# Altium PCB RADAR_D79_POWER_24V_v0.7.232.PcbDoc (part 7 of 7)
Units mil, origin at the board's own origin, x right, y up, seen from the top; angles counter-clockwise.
Board outline 3110.24 x 3110.24 mil, 8 copper layers (Top Layer, GND1, SIG1, PWR1, PWR2, SIG2, GND2, Bottom Layer), stack 55.2 mil thick; 304 components, 269 nets, 1408 pads, 1367 vias.
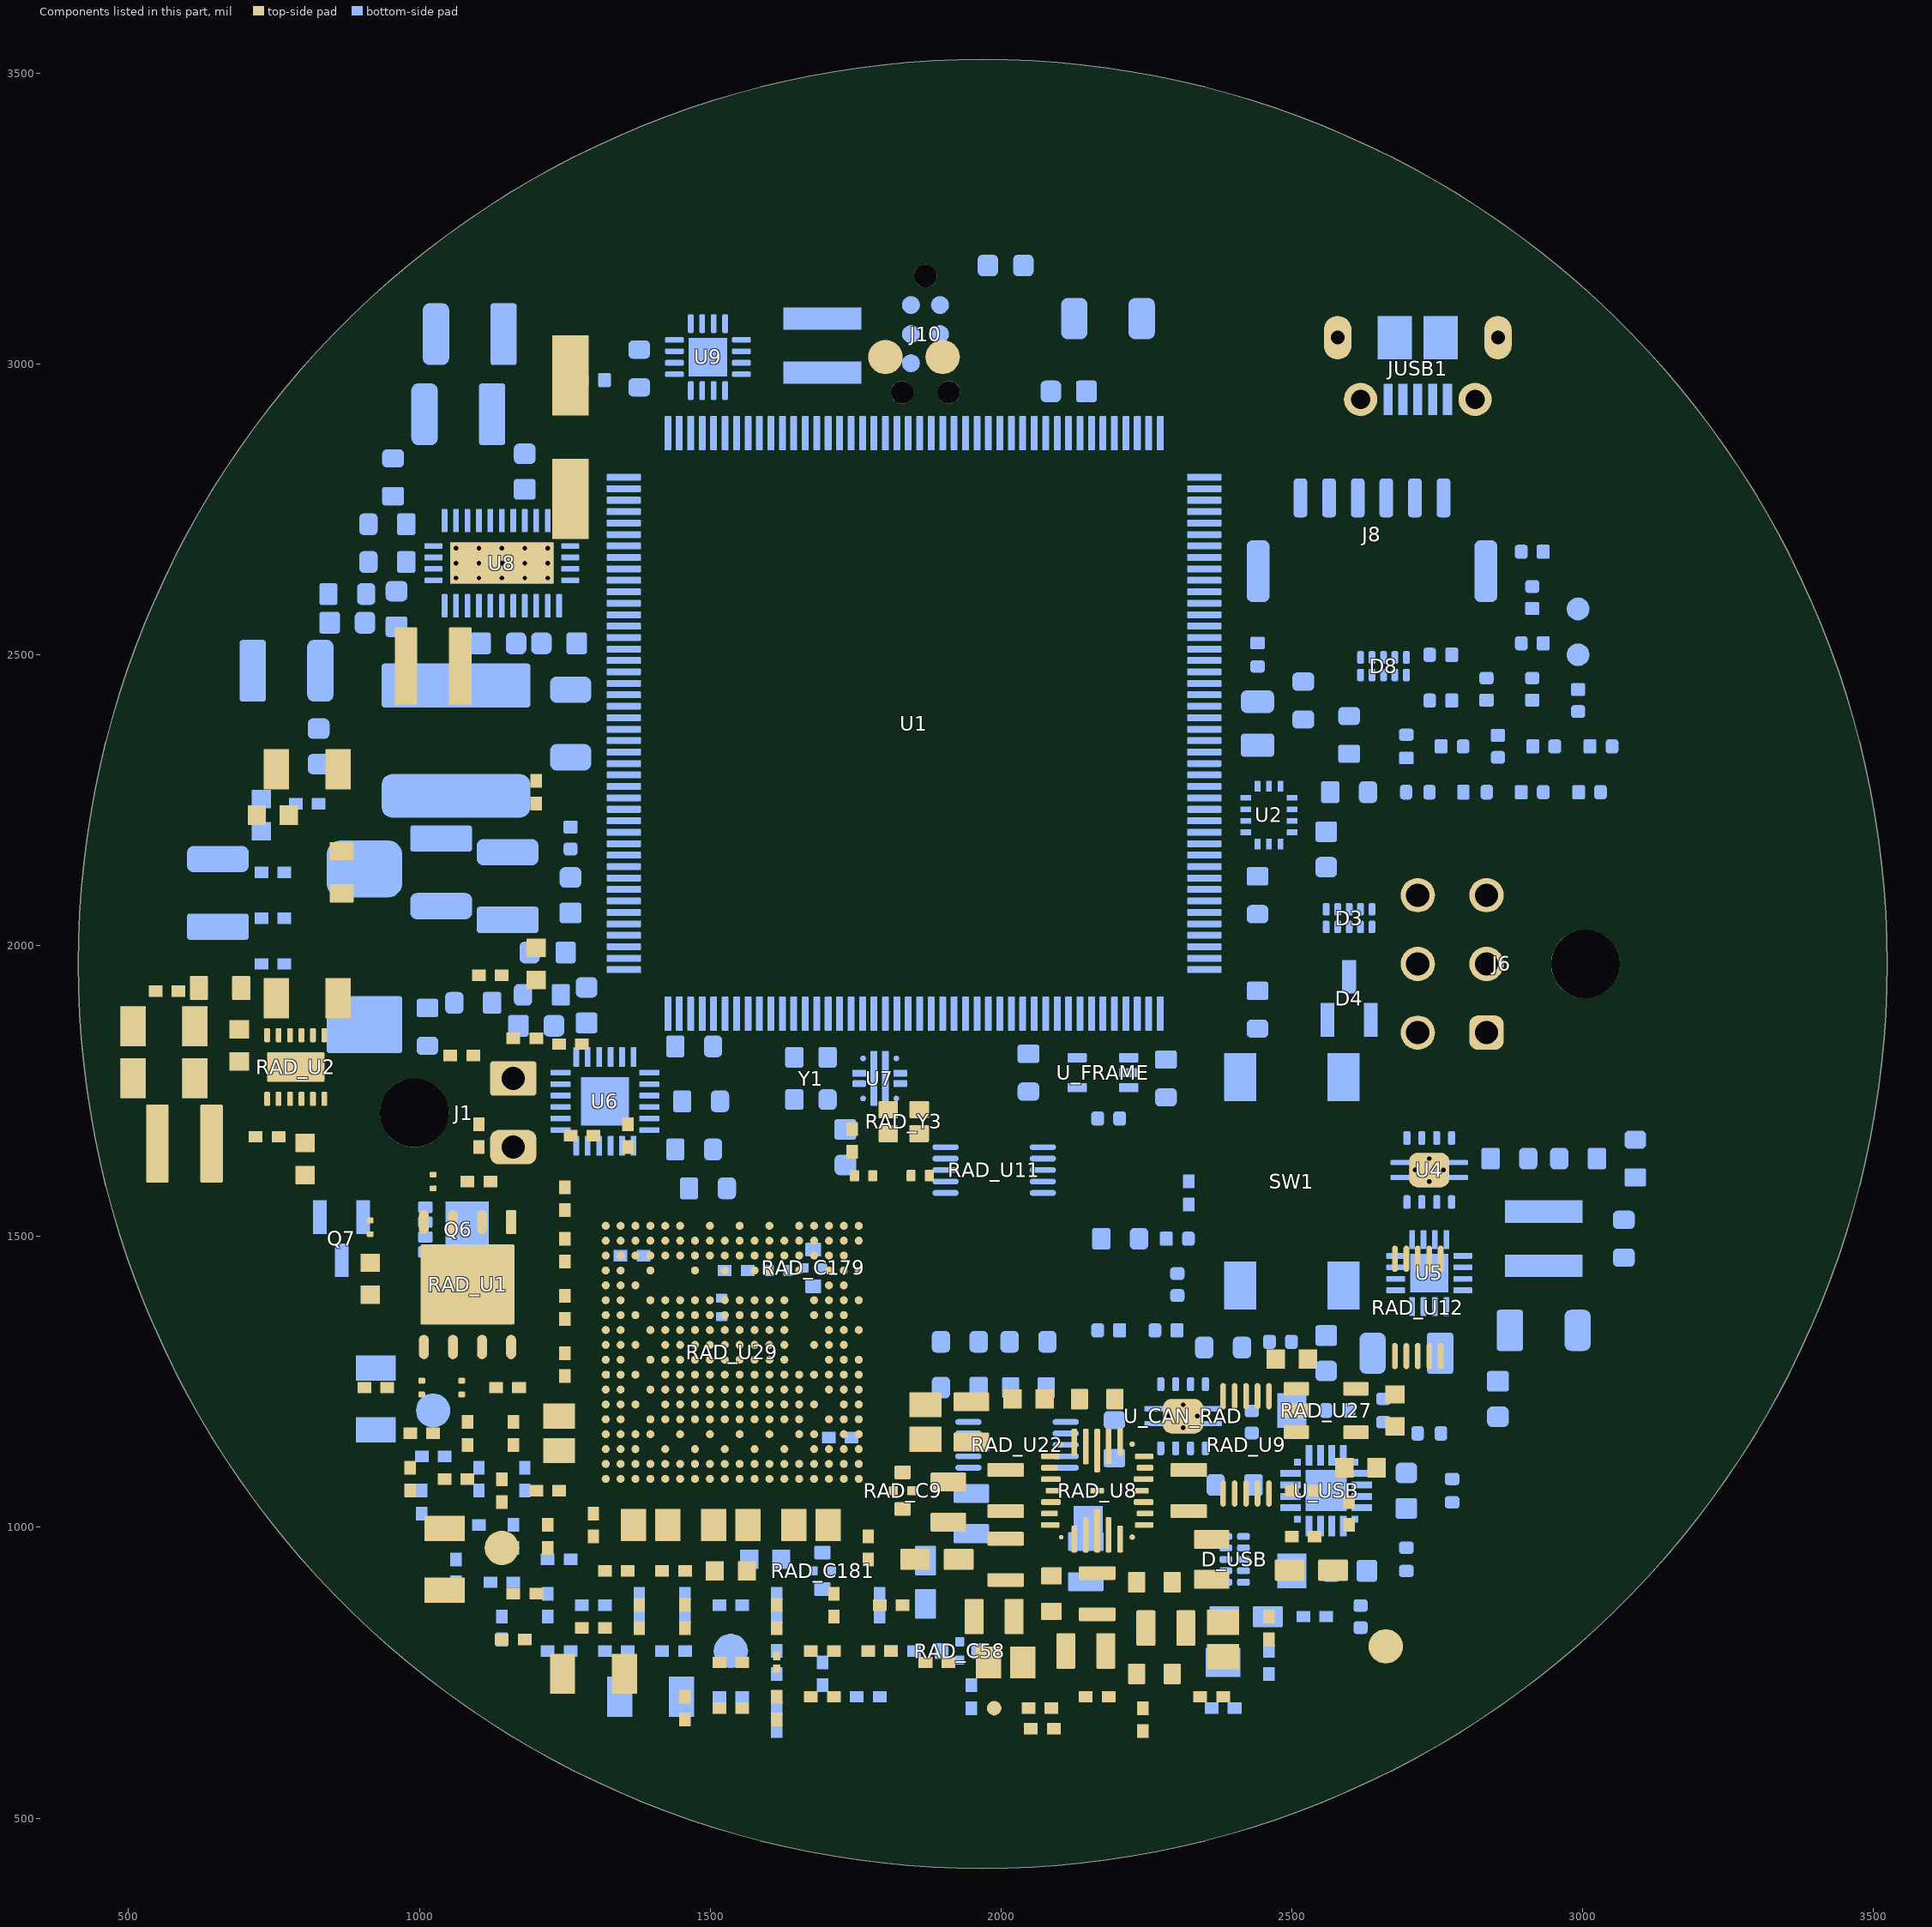
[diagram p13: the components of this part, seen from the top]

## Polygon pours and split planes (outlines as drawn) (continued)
TI_REGOUT_3V3 on PWR2 "REGOUT_3V3_WINDOW_9" (solid, pour order 9): 1746.1,974.42 1751.26,971.78 1756.65,969.65 1762.23,968.07 1767.93,967.03 1773.7,966.57 1779.5,966.66 1785.26,967.33 1790.92,968.56 1796.44,970.34 1801.75,972.65 1806.82,975.47 1811.58,978.77 1815.99,982.52 1820.02,986.69 1823.62,991.23 1826.76,996.1 1829.4,1001.26 1831.53,1006.65 1833.11,1012.23 1834.15,1017.93 1834.62,1023.7 1834.52,1029.5 1833.85,1035.26 1832.62,1040.92 1830.84,1046.44 1828.53,1051.75 1825.72,1056.82 1822.41,1061.58 1818.66,1065.99 1814.49,1070.02 1809.95,1073.62 1805.08,1076.76 1678.97,1149.43 1673.81,1152.08 1668.42,1154.2 1662.85,1155.79 1657.14,1156.82 1651.37,1157.29 1645.57,1157.19 1639.81,1156.53 1634.15,1155.3 1628.63,1153.52 1623.32,1151.21 1618.26,1148.39 1613.49,1145.09 1609.08,1141.34 1605.05,1137.17 1601.45,1132.63 1598.31,1127.76 1595.67,1122.6 1593.54,1117.21 1591.96,1111.63 1590.92,1105.93 1590.46,1100.15 1590.55,1094.36 1591.22,1088.6 1592.45,1082.94 1594.23,1077.42 1596.54,1072.11 1599.36,1067.04 1602.66,1062.28 1606.41,1057.86 1610.58,1053.84 1615.12,1050.24 1619.99,1047.1
TI_REGOUT_3V3 on PWR2 "REGOUT_3V3_WINDOW_10" (solid, pour order 10): 1580.31,1178.91 1582.2,1178.48 1584.12,1178.24 1586.05,1178.19 1587.97,1178.34 1589.88,1178.66 1591.74,1179.18 1593.54,1179.87 1595.27,1180.74 1596.9,1181.77 1598.42,1182.96 1599.83,1184.29 1601.09,1185.75 1602.2,1187.33 1603.15,1189.01 1603.94,1190.78 1604.55,1192.61 1604.97,1194.49 1605.21,1196.41 1605.26,1198.34 1605.12,1200.27 1604.79,1202.17 1604.27,1204.03 1603.58,1205.84 1602.71,1207.56 1601.68,1209.2 1600.49,1210.72 1599.16,1212.12 1597.7,1213.38 1596.12,1214.5 1594.44,1215.45 1592.68,1216.23 1590.84,1216.84 1380.7,1275.17 1378.81,1275.59 1376.9,1275.83 1374.96,1275.88 1373.04,1275.74 1371.13,1275.41 1369.27,1274.9 1367.47,1274.2 1365.74,1273.34 1364.11,1272.3 1362.59,1271.12 1361.19,1269.79 1359.92,1268.32 1358.81,1266.74 1357.86,1265.06 1357.07,1263.3 1356.47,1261.47 1356.04,1259.58 1355.8,1257.66 1355.75,1255.73 1355.89,1253.81 1356.22,1251.9 1356.74,1250.04 1357.43,1248.24 1358.3,1246.51 1359.33,1244.88 1360.52,1243.35 1361.85,1241.95 1363.31,1240.69 1364.89,1239.58 1366.57,1238.62 1368.33,1237.84 1370.17,1237.23
TI_REGOUT_3V3 on PWR2 "REGOUT_3V3_WINDOW_11" (solid, pour order 11): 1619.9,1154.71 1621.61,1153.81 1623.4,1153.08 1625.25,1152.53 1627.15,1152.16 1629.07,1151.99 1631,1152 1632.93,1152.2 1634.82,1152.59 1636.66,1153.16 1638.44,1153.91 1640.14,1154.83 1641.74,1155.91 1643.23,1157.15 1644.59,1158.52 1645.8,1160.02 1646.87,1161.63 1647.77,1163.34 1648.49,1165.13 1649.04,1166.98 1649.41,1168.88 1649.59,1170.8 1649.58,1172.74 1649.38,1174.66 1648.99,1176.55 1648.42,1178.4 1647.67,1180.18 1646.75,1181.87 1645.66,1183.47 1644.43,1184.96 1643.05,1186.32 1641.55,1187.53 1639.94,1188.6 1595.6,1214.82 1593.89,1215.72 1592.1,1216.45 1590.25,1217 1588.35,1217.36 1586.43,1217.54 1584.5,1217.53 1582.57,1217.33 1580.68,1216.94 1578.84,1216.37 1577.06,1215.62 1575.36,1214.7 1573.76,1213.61 1572.27,1212.38 1570.91,1211.01 1569.7,1209.51 1568.63,1207.89 1567.73,1206.18 1567.01,1204.39 1566.46,1202.54 1566.09,1200.65 1565.91,1198.72 1565.92,1196.79 1566.12,1194.87 1566.51,1192.98 1567.08,1191.13 1567.83,1189.35 1568.75,1187.65 1569.84,1186.05 1571.07,1184.57 1572.45,1183.21 1573.95,1181.99 1575.56,1180.93
TI_REGOUT_3V3 on PWR2 "REGOUT_3V3_WINDOW_12" (solid, pour order 12): 1761.65,1011.69 1763.08,1010.39 1764.63,1009.24 1766.29,1008.24 1768.03,1007.41 1769.85,1006.76 1771.72,1006.29 1773.63,1006 1775.56,1005.91 1777.49,1006 1779.4,1006.28 1781.28,1006.75 1783.1,1007.39 1784.85,1008.22 1786.5,1009.21 1788.06,1010.36 1789.49,1011.65 1790.79,1013.08 1791.94,1014.63 1792.94,1016.29 1793.77,1018.03 1794.42,1019.85 1794.89,1021.72 1795.18,1023.63 1795.28,1025.56 1795.18,1027.49 1794.9,1029.4 1794.44,1031.28 1793.79,1033.1 1792.96,1034.85 1791.97,1036.5 1790.82,1038.06 1789.53,1039.49 1643.86,1185.55 1642.43,1186.85 1640.88,1188.01 1639.22,1189 1637.48,1189.83 1635.66,1190.48 1633.79,1190.96 1631.88,1191.24 1629.95,1191.34 1628.02,1191.25 1626.11,1190.97 1624.23,1190.5 1622.41,1189.85 1620.67,1189.03 1619.01,1188.04 1617.45,1186.89 1616.02,1185.59 1614.72,1184.16 1613.57,1182.61 1612.57,1180.96 1611.74,1179.21 1611.09,1177.39 1610.62,1175.52 1610.33,1173.61 1610.24,1171.68 1610.33,1169.75 1610.61,1167.84 1611.08,1165.96 1611.72,1164.14 1612.55,1162.4 1613.54,1160.74 1614.69,1159.19 1615.98,1157.75
TI_REGOUT_3V3 on PWR2 "REGOUT_3V3_WINDOW_13" (solid, pour order 13): 1513.98,1087.64 1517.05,1085.29 1520.33,1083.26 1523.8,1081.56 1527.42,1080.2 1531.15,1079.21 1534.97,1078.59 1538.82,1078.35 1542.68,1078.48 1546.51,1078.99 1550.27,1079.88 1553.93,1081.13 1557.45,1082.73 1560.79,1084.67 1563.92,1086.93 1566.82,1089.48 1569.46,1092.31 1571.8,1095.38 1573.84,1098.66 1575.54,1102.13 1576.89,1105.75 1577.88,1109.49 1578.5,1113.3 1578.75,1117.15 1578.61,1121.02 1578.1,1124.85 1577.22,1128.61 1575.97,1132.26 1574.36,1135.78 1572.42,1139.12 1570.17,1142.25 1567.61,1145.15 1564.79,1147.79 1400.84,1286.28 1397.77,1288.62 1394.48,1290.66 1391.01,1292.36 1387.39,1293.71 1383.66,1294.7 1379.85,1295.32 1375.99,1295.57 1372.13,1295.43 1368.3,1294.92 1364.54,1294.03 1360.88,1292.78 1357.37,1291.18 1354.03,1289.24 1350.89,1286.99 1347.99,1284.43 1345.36,1281.61 1343.01,1278.54 1340.98,1275.25 1339.28,1271.78 1337.92,1268.16 1336.93,1264.43 1336.31,1260.62 1336.07,1256.76 1336.2,1252.9 1336.71,1249.07 1337.6,1245.31 1338.85,1241.65 1340.45,1238.14 1342.39,1234.79 1344.65,1231.66 1347.2,1228.76 1350.03,1226.12
TI_REGOUT_3V3 on PWR2 "REGOUT_3V3_WINDOW_14" (solid, pour order 14): 1565.21,1058.46 1568.68,1056.76 1572.3,1055.4 1576.03,1054.41 1579.84,1053.79 1583.7,1053.55 1587.56,1053.68 1591.39,1054.2 1595.15,1055.08 1598.81,1056.33 1602.32,1057.93 1605.66,1059.87 1608.8,1062.13 1611.7,1064.69 1614.33,1067.51 1616.68,1070.58 1618.71,1073.87 1620.41,1077.34 1621.76,1080.96 1622.75,1084.69 1623.37,1088.5 1623.62,1092.36 1623.48,1096.22 1622.97,1100.05 1622.08,1103.81 1620.83,1107.47 1619.23,1110.98 1617.29,1114.32 1615.03,1117.46 1612.48,1120.36 1609.65,1122.99 1606.58,1125.34 1603.3,1127.37 1558.43,1152.17 1554.96,1153.87 1551.34,1155.22 1547.6,1156.21 1543.79,1156.84 1539.93,1157.08 1536.07,1156.94 1532.24,1156.43 1528.48,1155.54 1524.83,1154.29 1521.31,1152.69 1517.97,1150.75 1514.84,1148.49 1511.94,1145.94 1509.3,1143.11 1506.96,1140.04 1504.92,1136.76 1503.22,1133.29 1501.87,1129.67 1500.88,1125.93 1500.26,1122.12 1500.02,1118.27 1500.15,1114.4 1500.66,1110.57 1501.55,1106.81 1502.8,1103.16 1504.4,1099.64 1506.34,1096.3 1508.6,1093.17 1511.15,1090.27 1513.98,1087.63 1517.05,1085.29 1520.34,1083.26
TI_REGOUT_3V3 on PWR2 "REGOUT_3V3_WINDOW_15" (solid, pour order 15): 1681.59,1048.86 1685.46,1048.87 1689.3,1049.25 1693.09,1050.01 1696.78,1051.14 1700.35,1052.62 1703.76,1054.45 1706.96,1056.6 1709.95,1059.06 1712.68,1061.79 1715.12,1064.78 1717.26,1068 1719.08,1071.41 1720.55,1074.98 1721.67,1078.68 1722.42,1082.47 1722.79,1086.32 1722.78,1090.18 1722.4,1094.02 1721.64,1097.81 1720.51,1101.51 1719.03,1105.08 1717.2,1108.48 1715.05,1111.69 1712.6,1114.67 1709.86,1117.4 1706.87,1119.85 1703.65,1121.99 1700.24,1123.8 1696.67,1125.28 1692.97,1126.39 1689.18,1127.14 1685.34,1127.51 1586.12,1132.24 1582.26,1132.23 1578.42,1131.85 1574.63,1131.09 1570.93,1129.96 1567.37,1128.48 1563.96,1126.65 1560.75,1124.5 1557.77,1122.04 1555.04,1119.31 1552.59,1116.32 1550.45,1113.1 1548.64,1109.69 1547.16,1106.12 1546.05,1102.42 1545.3,1098.63 1544.93,1094.79 1544.93,1090.92 1545.32,1087.08 1546.08,1083.29 1547.2,1079.59 1548.69,1076.03 1550.51,1072.62 1552.66,1069.41 1555.12,1066.43 1557.86,1063.7 1560.85,1061.26 1564.06,1059.11 1567.47,1057.3 1571.04,1055.82 1574.74,1054.71 1578.53,1053.96 1582.38,1053.59
TI_REGOUT_3V3 on PWR2 "REGOUT_3V3_WINDOW_16" (solid, pour order 16): 1753.46,993.03 1756.76,991.01 1760.24,989.34 1763.87,988.01 1767.61,987.04 1771.43,986.44 1775.28,986.22 1779.14,986.38 1782.97,986.92 1786.73,987.83 1790.37,989.1 1793.88,990.73 1797.21,992.69 1800.33,994.96 1803.21,997.54 1805.83,1000.38 1808.15,1003.46 1810.17,1006.76 1811.85,1010.24 1813.18,1013.87 1814.14,1017.61 1814.74,1021.43 1814.96,1025.28 1814.8,1029.14 1814.26,1032.97 1813.35,1036.73 1812.08,1040.37 1810.46,1043.88 1808.49,1047.21 1806.22,1050.33 1803.65,1053.21 1800.8,1055.83 1797.72,1058.15 1705.59,1120.75 1702.29,1122.76 1698.81,1124.44 1695.19,1125.77 1691.45,1126.74 1687.63,1127.34 1683.77,1127.56 1679.91,1127.4 1676.08,1126.86 1672.33,1125.95 1668.68,1124.68 1665.18,1123.05 1661.85,1121.09 1658.73,1118.82 1655.84,1116.24 1653.23,1113.4 1650.9,1110.32 1648.89,1107.02 1647.21,1103.54 1645.88,1099.91 1644.91,1096.17 1644.32,1092.35 1644.1,1088.5 1644.26,1084.63 1644.79,1080.81 1645.7,1077.05 1646.98,1073.41 1648.6,1069.9 1650.56,1066.57 1652.84,1063.45 1655.41,1060.57 1658.25,1057.95 1661.34,1055.63
GND on Bottom Layer "GND_BOTTOM_RETURN" (solid, remove dead copper, pour order 5): 3474.41,1968.5 3472.98,2034.19 3468.68,2099.75 3461.53,2165.06 3451.53,2230 3438.71,2294.44 3423.1,2358.26 3404.71,2421.34 3383.59,2483.55 3359.78,2544.79 3333.32,2604.93 3304.26,2663.85 3272.66,2721.46 3238.57,2777.63 3202.07,2832.26 3163.22,2885.24 3122.09,2936.48 3078.77,2985.88 3033.34,3033.34 2985.88,3078.77 2936.48,3122.09 2885.24,3163.22 2832.26,3202.07 2777.63,3238.57 2721.46,3272.66 2663.85,3304.26 2604.93,3333.32 2544.79,3359.78 2483.55,3383.59 2421.34,3404.71 2358.26,3423.1 2294.44,3438.71 2230,3451.53 2165.06,3461.53 2099.75,3468.68 2034.19,3472.98 1968.5,3474.41 1902.82,3472.98 1837.26,3468.68 1771.94,3461.53 1707.01,3451.53 1642.57,3438.71 1578.75,3423.1 1515.67,3404.71 1453.45,3383.59 1392.22,3359.78 1332.08,3333.32 1273.15,3304.26 1215.55,3272.66 1159.38,3238.57 1104.75,3202.07 1051.77,3163.22 1000.53,3122.09 951.13,3078.77 903.67,3033.34 858.23,2985.88 814.91,2936.48 773.79,2885.24 734.94,2832.26 698.44,2777.63 664.35,2721.46 632.75,2663.85 603.69,2604.93 577.23,2544.79 553.42,2483.55 532.3,2421.34 513.91,2358.26 498.29,2294.44 485.48,2230 475.48,2165.06 468.33,2099.75 464.03,2034.19 462.6,1968.5 464.03,1902.82 468.33,1837.26 475.48,1771.94 485.48,1707.01 498.29,1642.57 513.91,1578.75 532.3,1515.67 553.42,1453.45 577.23,1392.22 603.69,1332.08 632.75,1273.15 664.35,1215.55 698.44,1159.38 734.94,1104.75 773.79,1051.77 814.91,1000.53 858.23,951.13 903.67,903.67 951.13,858.23 1000.53,814.91 1051.77,773.79 1104.75,734.94 1159.38,698.44 1215.55,664.35 1273.15,632.75 1332.08,603.69 1392.22,577.23 1453.45,553.42 1515.67,532.3 1578.75,513.91 1642.57,498.29 1707.01,485.48 1771.94,475.48 1837.26,468.33 1902.82,464.03 1968.5,462.6 2034.19,464.03 2099.75,468.33 2165.06,475.48 2230,485.48 2294.44,498.29 2358.26,513.91 2421.34,532.3 2483.55,553.42 2544.79,577.23 2604.93,603.69 2663.85,632.75 2721.46,664.35 2777.63,698.44 2832.26,734.94 2885.24,773.79 2936.48,814.91 2985.88,858.23 3033.34,903.67 3078.77,951.13 3122.09,1000.53 3163.22,1051.77 3202.07,1104.75 3238.57,1159.38 3272.66,1215.55 3304.26,1273.15 3333.32,1332.08 3359.78,1392.22 3383.59,1453.45 3404.71,1515.67 3423.1,1578.75 3438.71,1642.57 3451.53,1707.01 3461.53,1771.94 3468.68,1837.26 3472.98,1902.82
GND on GND1 "GND1_REFERENCE" (solid, remove dead copper, pour order 3): 2635.41,3327.06 2608.25,3340.45 2547.8,3367.05 2486.25,3390.99 2423.71,3412.22 2360.3,3430.7 2296.15,3446.4 2231.37,3459.29 2166.09,3469.33 2100.44,3476.52 2034.53,3480.84 1968.5,3482.28 1902.47,3480.84 1836.57,3476.52 1770.92,3469.33 1705.64,3459.29 1640.86,3446.4 1576.71,3430.7 1513.3,3412.22 1450.76,3390.99 1389.21,3367.05 1328.75,3340.45 1269.52,3311.24 1211.61,3279.48 1155.15,3245.21 1100.24,3208.52 1046.97,3169.47 995.47,3128.13 945.81,3084.58 898.1,3038.91 852.43,2991.2 808.88,2941.54 767.54,2890.03 728.49,2836.77 691.8,2781.86 657.53,2725.39 625.77,2667.49 596.55,2608.25 569.95,2547.8 546.02,2486.25 524.79,2423.71 506.31,2360.3 490.61,2296.15 477.72,2231.37 467.68,2166.09 460.48,2100.44 456.17,2034.53 454.72,1968.5 456.17,1902.47 460.48,1836.57 467.68,1770.92 477.72,1705.64 490.61,1640.86 506.31,1576.71 524.79,1513.3 546.02,1450.76 569.95,1389.21 596.55,1328.75 625.77,1269.52 657.53,1211.61 691.8,1155.15 728.49,1100.24 767.54,1046.97 808.88,995.47 852.43,945.81 898.1,898.1 945.81,852.43 995.47,808.88 1046.97,767.54 1100.24,728.49 1155.15,691.8 1211.61,657.53 1269.52,625.77 1328.75,596.55 1389.21,569.95 1450.76,546.02 1513.3,524.79 1576.71,506.31 1640.86,490.61 1705.64,477.72 1770.92,467.68 1836.57,460.48 1902.47,456.17 1968.5,454.72 2034.53,456.17 2100.44,460.48 2166.09,467.68 2231.37,477.72 2296.15,490.61 2360.3,506.31 2423.71,524.79 2486.25,546.02 2547.8,569.95 2608.25,596.55 2635.41,609.94

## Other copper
Top Layer:
  rectangle net TI_RX1: 1420.7,1961.62 1456.13,2004.14
  rectangle net TI_RX1: 1411.84,2036.42 1464.99,2078.94
  rectangle net TI_RX2: 1495.5,1961.62 1530.93,2004.14
  rectangle net TI_RX2: 1486.64,2036.42 1539.79,2078.94
  rectangle net TI_RX3: 1570.3,1961.62 1605.74,2004.14
  rectangle net TI_RX3: 1561.45,2036.42 1614.59,2078.94
  rectangle net TI_RX4: 1645.11,1961.62 1680.54,2004.14
  rectangle net TI_RX4: 1636.25,2036.42 1689.4,2078.94
  rectangle net TI_TX1: 1912.02,1968.57 1947.45,2011.08
  rectangle net TI_TX1: 1903.16,2043.37 1956.31,2085.89
  rectangle net TI_TX2: 2066.27,2091.99 2101.71,2134.51
  rectangle net TI_TX2: 2057.41,2166.79 2110.56,2209.31
  rectangle net TI_TX3: 2220.56,1968.57 2256,2011.08
  rectangle net TI_TX3: 2211.71,2043.37 2264.86,2085.89
  rectangle net TI_TX4: 2529.11,1968.57 2564.54,2011.08
  rectangle net TI_TX4: 2520.25,2043.37 2573.4,2085.89

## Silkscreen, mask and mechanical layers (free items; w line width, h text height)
M1 Board Outline:
  circle w3.94: c1968.5,1968.5 r1555.12
M2 Board Dimensions:
  lines w6.3: 1332.75,1735.72 1409.87,1735.72 1409.87,1623.56 1451.09,1582.35 1451.09,1537.98 1454.62,1534.44 1465.76,1534.44 1465.76,1507.74 1478.4,1507.74 1481.94,1511.28 1481.94,1534.44 1516.89,1534.44 1516.89,1507.74 1529.63,1507.74 1533.16,1511.28 1533.16,1534.44 1568.07,1534.44 1568.07,1507.74 1584.35,1507.74 1584.35,1534.44 1619.34,1534.44 1619.34,1507.74 1635.67,1507.74 1635.67,1535.6 1685.26,1585.19 1685.26,1629.06 1700.22,1644.02 1700.22,1813.89 1850.79,1813.89 1938.06,1726.62 1938.06,1565.78 1874.58,1502.3 1847.63,1502.3 1842.57,1497.24 1771.99,1497.24 1771.99,1475.16 1746.18,1475.16 1746.18,1458.97 1771.99,1458.97 1771.99,1424.03 1746.18,1424.03 1746.18,1407.79 1771.99,1407.79 1771.99,1372.89 1746.18,1372.89 1746.18,1360.15 1749.72,1356.61 1771.99,1356.61 1771.99,1321.71 1746.18,1321.71 1746.18,1305.43 1771.99,1305.43 1771.99,1287.99 2635.41,1287.99 2635.41,2872.45 1332.75,2872.45 1332.75,1735.72
  text "RF WINDOW REF" at 1456.69,1732.28 h41.34
M3 3D STEP Top:
  lines w6.3: 1222.86,985.81 1852.78,985.81 1852.78,1615.74 1222.86,1615.74 1222.86,985.81 ; 2472.44,944.88 2755.91,944.88 2755.91,1181.1 2472.44,1181.1 2472.44,944.88
  text "REAR HEAT RESERVE" at 1259.84,1181.1 h41.34
  text "USB BRIDGE RESERVE" at 2322.83,1141.73 h41.34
